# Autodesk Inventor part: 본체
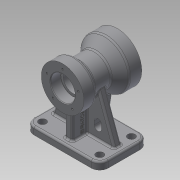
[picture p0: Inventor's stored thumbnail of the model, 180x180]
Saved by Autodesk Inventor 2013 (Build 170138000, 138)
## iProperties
Created: 2015-08
Part Number: 본체
Material: 일반
Document SubType Name: Modeling
Designer: ST
Density: 1 g/cm^3
Author: ST
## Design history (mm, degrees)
sketch "스케치1"
  geometry: L1 (-61, 40)-(61, 40); L2 (61, 40)-(61, -40); L3 (61, -40)-(-61, -40); L4 (-61, -40)-(-61, 40); 1 further point
  constraints: 8 end point, 2 parallel, 1 horizontal, 1 perpendicular
  dimensions: "d0" = 122 distance between parallel lines of L2 L4; "d2" = 61 distance from line of point (0, 0) L4; "d3" = 80 distance between parallel lines of L3 L1; "d4" = 40 distance from line of point (0, 0) L1
extrude "돌출1" new body sketch "스케치1" distance "d5" = 12; taper "d6" = 0 deg
sketch "스케치4"
  geometry: L1 (-40, 90)-(50, 90); L2 (-40, 125)-(-20, 125); L3 (-20, 125)-(-14.804, 116); L4 (-14.804, 116)-(13.315, 116); L5 (13.315, 116)-(30, 130); L6 (30, 130)-(50, 130); L7 (50, 130)-(50, 90); L8 (-40, 125)-(-40, 90); L9 (-40, 0)-(-40, 12) reference; 1 further point
  constraints: 16 end point, 4 parallel, 1 horizontal, 1 perpendicular
  dimensions: "d8" = 90 distance from line of point (0, 0) L1; "d10" = 70 diameter of L2 L1; "d11" = 80 diameter of L6 L1; "d12" = 52 diameter of L4 L1; "d13" = 90 distance between parallel lines of L7 L8; "d14" = 60 deg angle of L4 L3; "d15" = 40 deg angle of L4 L5; "d16" = 20 distance of L2.start L2.end; "d17" = 20 distance of L5.end L6.end; "d18" = 0 distance between parallel lines of L9 L8
revolve "회전1" sketch "스케치4" stored, may be unused: angle "d19" = 90 deg
fillet "모깎기1" dims "d20" = 14
sketch "스케치5"
  geometry: L1 (-30, 11.583)-(-30, 57.618); L2 (-40, 0)-(-40, 12) reference; L3 (30, 9.004)-(30, 12); L4 (40, 12)-(40, 0) reference; L5 (26, 12)-(40, 12) reference; L6 (30, 12)-(37.543, 54.776); L7 (-8.897, 12)-(-8.897, 64); L8 (1.694, 64)-(1.694, 12); L9 (-14.804, 64)-(13.315, 64) reference; L10 (-8.897, 64)-(1.694, 64); L11 (-8.897, 12)-(1.694, 12); 1 further point
  constraints: 14 end point, 3 point on line, 2 parallel, 1 collinear, 1 perpendicular, 1 vertical
  dimensions: "d21" = 10 distance between parallel lines of L1 L2; "d22" = 10 distance between parallel lines of L4 L3; "d23" = 80 deg angle of L5 L6; "d24" = 12 vertical distance of point (0, 0) L7.start; "d25" = 12 vertical distance of point (0, 0) L8.end
sketch "스케치6"
  geometry: L1 (-6, 6)-(6, 6); L2 (6, 6)-(6, -6); L3 (6, -6)-(-6, -6); L4 (-6, -6)-(-6, 6); 1 further point
  constraints: 8 end point, 2 parallel, 1 horizontal, 1 perpendicular
  dimensions: "d26" = 12 distance between parallel lines of L2 L4; "d28" = 6 distance from line of point (0, 0) L4; "d29" = 12 distance between parallel lines of L3 L1; "d30" = 6 distance from line of point (0, 0) L1
extrude "돌출2" join sketch "스케치6" stored distance "d31" = 12; taper "d32" = 0 deg
feature "리브1" dims "d33" = 1, "d34" = 12, "d35" = 0, "d36" = 0, "d37" = 1, "d38" = 1
feature "리브2" dims "d39" = 1, "d40" = 12, "d41" = 0, "d42" = 0, "d43" = 1, "d44" = 1
sketch "스케치7"
  geometry: L1 (51, 12)-(23.395, 87.843); L2 (47, 12)-(61, 12) reference; L3 (61, 12)-(61, 0) reference; 1 further point
  constraints: 2 end point
  dimensions: "d45" = 0 distance from line of L1.start L2; "d46" = 10 distance from line of L3 L1.start; "d47" = 70 deg angle of L2 L1
feature "리브3" sketch "스케치7" dims "d48" = 1, "d49" = 12, "d50" = 0, "d51" = 0, "d52" = 1, "d53" = 1
fillet "모깎기2" dims "d54" = 5
sketch "스케치8"
  geometry: C1 r 40 at (0, 0) reference; C2 r 26 at (0, 0); 1 further point
  constraints: 1 centre point, 1 coincident
  dimensions: "d55" = 52 diameter of C2
extrude "돌출3" cut sketch "스케치8" distance "d57" = 20; taper "d58" = 0 deg
sketch "스케치9"
  geometry: C1 r 26 at (0, 0) reference; C2 r 19 at (0, 0); 1 further point
  constraints: 1 centre point, 1 coincident
  dimensions: "d59" = 38 diameter of C2
extrude "돌출4" cut sketch "스케치9" distance "d61" = 3; taper "d62" = 0 deg
sketch "스케치10"
  geometry: C1 r 35 at (0, 0) reference; C2 r 20 at (0, 0); 1 further point
  constraints: 1 centre point, 1 coincident
  dimensions: "d63" = 40 diameter of C2
extrude "돌출5" cut sketch "스케치10" distance "d65" = 17; taper "d66" = 0 deg
sketch "스케치11"
  geometry: C1 r 20 at (0, 0) reference; C2 r 16 at (0, 0); 1 further point
  constraints: 1 centre point, 1 coincident
  dimensions: "d67" = 32 diameter of C2
extrude "돌출6" cut sketch "스케치11" stored distance "d69" = 17; taper "d70" = 0 deg
fillet "모깎기3" dims "d71" = 3
fillet "모깎기4" dims "d72" = 3
fillet "모깎기5" dims "d73" = 3
fillet "모깎기6" dims "d74" = 3
fillet "모깎기7" dims "d75" = 0.3
chamfer "모따기1" distance "d76" = 1; stored, may be unused: second distance "d77" = 2, angle "d78" = 45 deg
sketch "스케치12"
  geometry: C1 r 6 at (-47, -26); A1 r 14 centre (-47, -26) between (-61, -26) and (-47, -40) reference; 1 further point
  constraints: 1 centre point, 1 coincident
  dimensions: "d79" = 12 diameter of C1
extrude "돌출7" cut sketch "스케치12" distance "d81" = 17; taper "d82" = 0 deg
sketch "스케치13"
  geometry: C1 r 6 at (-47, 26); C2 r 6 at (47, 26); C3 r 6 at (47, -26); A1 r 14 centre (47, -26) between (47, -40) and (61, -26) reference; A2 r 14 centre (47, 26) between (61, 26) and (47, 40) reference; A3 r 14 centre (-47, 26) between (-47, 40) and (-61, 26) reference; 1 further point
  constraints: 3 centre point, 3 coincident, 2 equal radius
  dimensions: "d83" = 12 diameter of C1
extrude "돌출8" cut sketch "스케치13" distance "d85" = 17; taper "d86" = 0 deg
sketch "스케치14"
  geometry: L1 (38, 15)-(-56, 15) reference; L2 (21, -21)-(21, -15); L3 (9, -21)-(9, -15); A1 r 6 centre (15, -15) between (21, -15) and (9, -15); A2 r 6 centre (15, -21) between (9, -21) and (21, -21); 1 further point
  constraints: 4 end point, 4 point on circle, 4 tangent, 2 centre point
  dimensions: "d87" = 30 distance from line of L1 A1.centre; "d88" = 24 horizontal distance of point (-9, 15) A1.centre; "d89" = 12 diameter of A1; "d90" = 12 diameter of A2; "d91" = 0 horizontal distance of A1.centre A2.centre; "d92" = 6 distance of A1.centre A2.centre
extrude "돌출9" cut sketch "스케치14" distance "d93" = 17; taper "d94" = 0 deg
sketch "스케치15" dims "d95" = 66
  geometry: C1 r 40 at (0, 0) reference; C2 r 27 at (0, 0) reference; 7 further points
  constraints: 1 coincident, 1 vertical alignment, 8 other
  dimensions: "d99" = 360 deg dimension on C1.centre point (0, -33) (derived)
hole "구멍1" sketch "스케치15" at (0, -33), (31.385, -10.198), (19.397, 26.698), (-19.397, 26.698), (-31.385, -10.198) diameter "d101" = 3.242; stored, may be unused: countersink angle "d105" = 90 deg, drill point angle "d107" = 118 deg; dims "d102" = 10, "d103" = 4, "d104" = 2, "d106" = 13
sketch "스케치16" dims "d108" = 54
  geometry: C1 r 35 at (0, 0) reference; C2 r 21 at (0, 0) reference; 7 further points
  constraints: 1 coincident, 1 vertical alignment, 8 other
  dimensions: "d112" = 360 deg dimension on C1.centre point (0, 27) (derived)
hole "구멍2" sketch "스케치16" at (0, 27), (-25.679, 8.343), (-15.87, -21.843), (15.87, -21.843), (25.679, 8.343) diameter "d114" = 3.242; stored, may be unused: countersink angle "d118" = 90 deg, drill point angle "d120" = 118 deg; dims "d115" = 10, "d116" = 4, "d117" = 2, "d119" = 13
node "작업 평면2"
sketch "스케치17"
  geometry: L1 (-0.261, 9.998)-(-41.739, 9.998); L2 (-41.739, 9.998)-(-41.739, 16.002); L3 (-41.739, 16.002)-(-0.261, 16.002); L4 (-0.261, 16.002)-(-0.261, 9.998); L5 (-0.261, 13)-(-41.739, 13); L6 (-21, 9.998)-(-21, 16.002); L7 (3, 1)-(3, 53) reference; L8 (-37.119, -3)-(0, -3) reference; 1 further point
  constraints: 4 end point, 4 midpoint, 2 other
  dimensions: "d122" = 24 distance between parallel lines of L7 L6; "d123" = 16 distance between parallel lines of L5 L8
feature "엠보싱1" sketch "스케치17" dims "d0" = 122, "d2" = 61, "d3" = 80, "d4" = 40, "d124" = 0.5, "d125" = 0
fillet "모깎기8" dims "d126" = 3
node "솔리드1"
mirror "대칭1"
mirror "대칭2"
other parameters: "d121" = 23.25
